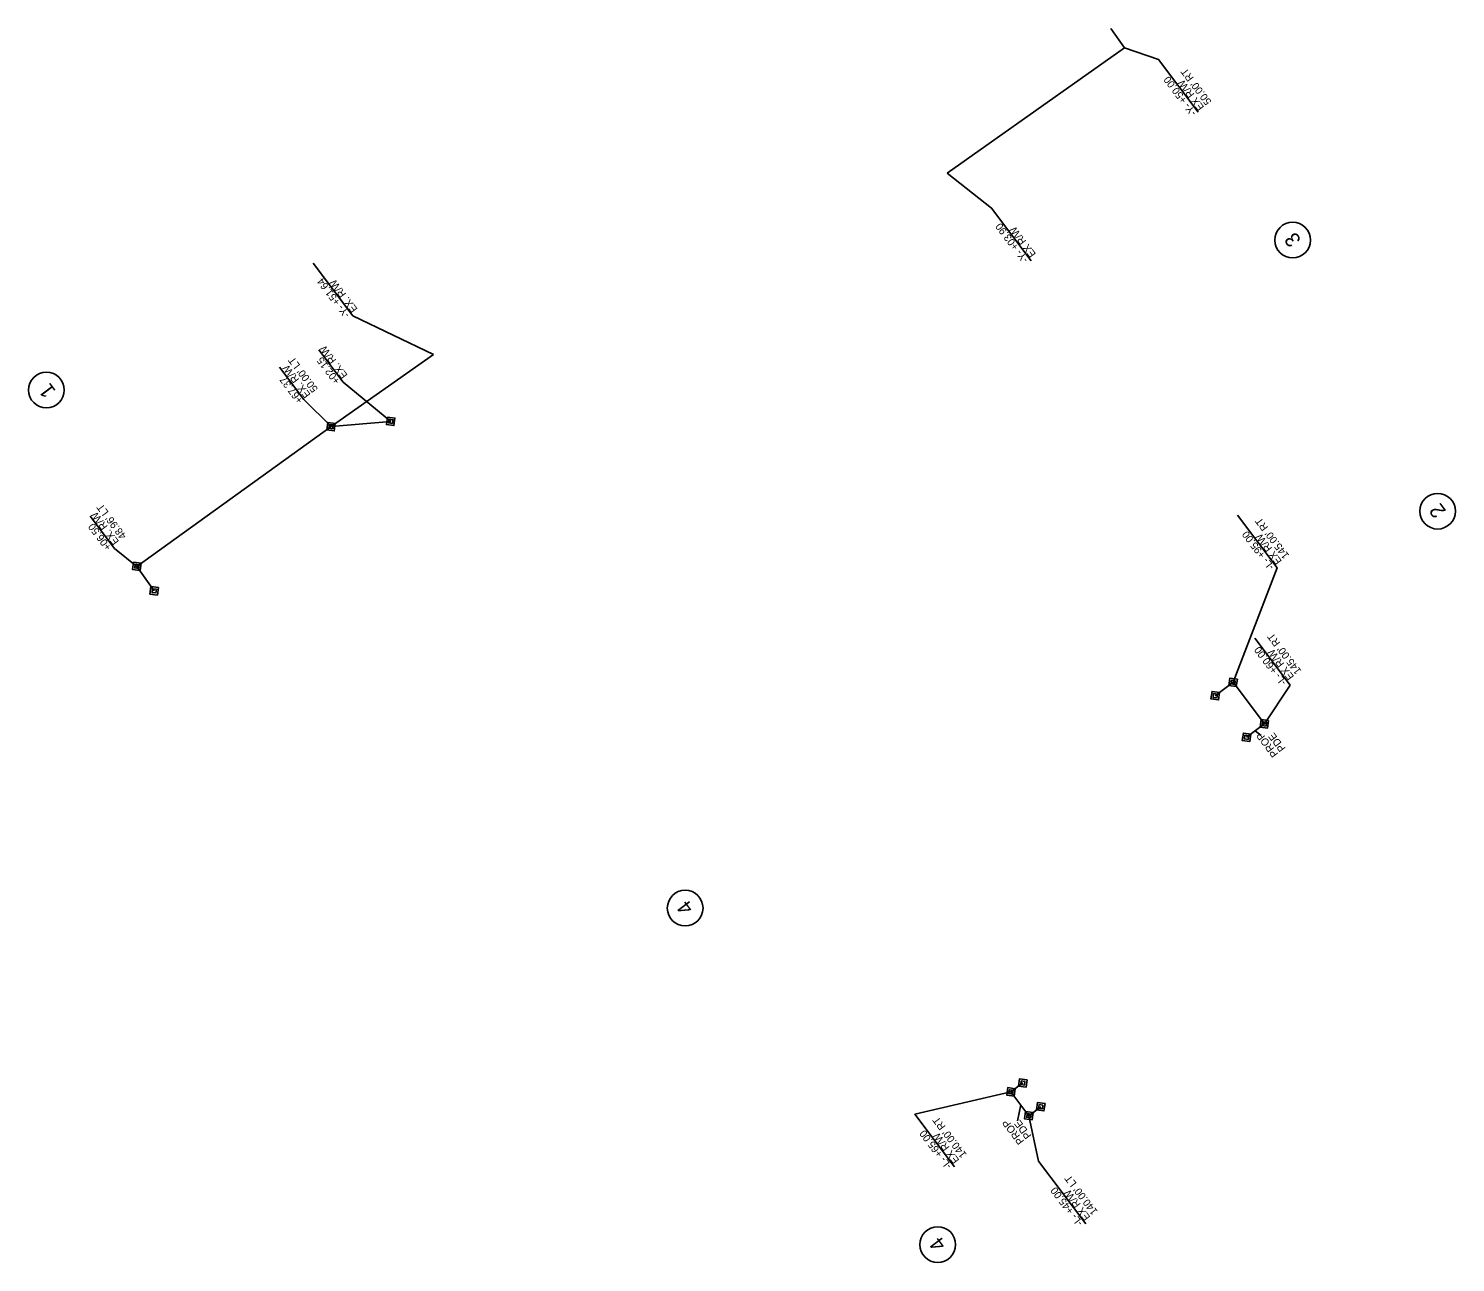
# Model space of a CAD drawing. Extents: x 1262953 to 1263913, y 775906 to 776736.
import ezdxf

# ---------------------------------------------------------------- set-up
doc = ezdxf.new("R2010")
doc.units = 0
for name, color, linetype in [('CTL Primary Horizontal and Vertical Cogo Elevation', 7, 'Continuous'), ('CTL Primary Horizontal and Vertical Cogo Number', 7, 'Continuous'), ('CTL Secondary Horizontal and Vertical CELL', 7, 'Continuous'), ('CTL Secondary Horizontal and Vertical Cogo Comment', 7, 'Continuous'), ('CTL Secondary Horizontal and Vertical Cogo Elevation', 7, 'Continuous'), ('CTL Secondary Horizontal and Vertical Cogo Number', 7, 'Continuous'), ('CTL Vertical Benchmark CELL', 7, 'Continuous'), ('CTL Vertical Benchmark Cogo Elevation', 7, 'Continuous'), ('CTL Vertical Benchmark Cogo Number', 7, 'Continuous')]:
    doc.layers.add(name, color=color, linetype=linetype)

msp = doc.modelspace()

# ---------------------------------------------------------------- linework, layer by layer
at = {"layer": 'CTL Primary Horizontal and Vertical Cogo Elevation'}
for p, q in [((1263156.87, 776467.92), (1263156.87, 776467.92)), ((1263196.98, 776471.45), (1263196.98, 776471.45)), ((1263026.3, 776373.94), (1263026.3, 776373.94)), ((1263037.95, 776357.47), (1263037.95, 776357.47)), ((1263763.41, 776295.97), (1263763.41, 776295.97)), ((1263751.43, 776286.95), (1263751.43, 776286.95)), ((1263784.47, 776268.02), (1263784.47, 776268.02)), ((1263772.49, 776258.99), (1263772.49, 776258.99)), ((1263622.05, 776026.56), (1263622.05, 776026.56)), ((1263614.07, 776020.55), (1263614.07, 776020.55)), ((1263626.1, 776004.57), (1263626.1, 776004.57)), ((1263634.09, 776010.59), (1263634.09, 776010.59))]:
    msp.add_line(p, q, dxfattribs=at)
for points in [[(1263194.8, 776474.31), (1263199.84, 776473.62), (1263199.16, 776468.58), (1263194.11, 776469.27)], [(1263159.73, 776470.09), (1263159.04, 776465.05), (1263154, 776465.74), (1263154.69, 776470.78)], [(1263158.3, 776469.01), (1263157.96, 776466.48), (1263155.43, 776466.83), (1263155.78, 776469.35)], [(1263195.89, 776472.88), (1263198.41, 776472.53), (1263198.07, 776470.01), (1263195.54, 776470.36)], [(1263024.12, 776376.81), (1263029.16, 776376.12), (1263028.47, 776371.08), (1263023.43, 776371.76)], [(1263025.21, 776375.38), (1263027.73, 776375.03), (1263027.39, 776372.51), (1263024.86, 776372.85)], [(1263035.77, 776360.34), (1263040.82, 776359.65), (1263040.13, 776354.61), (1263035.09, 776355.29)], [(1263036.86, 776358.9), (1263039.39, 776358.56), (1263039.04, 776356.04), (1263036.52, 776356.38)], [(1263766.28, 776298.15), (1263765.59, 776293.11), (1263760.55, 776293.79), (1263761.23, 776298.84)], [(1263764.84, 776297.06), (1263764.5, 776294.54), (1263761.98, 776294.88), (1263762.32, 776297.41)], [(1263754.29, 776289.13), (1263753.61, 776284.08), (1263748.56, 776284.77), (1263749.25, 776289.81)], [(1263752.86, 776288.04), (1263752.52, 776285.52), (1263750, 776285.86), (1263750.34, 776288.38)], [(1263787.33, 776270.19), (1263786.65, 776265.15), (1263781.6, 776265.84), (1263782.29, 776270.88)], [(1263785.9, 776269.11), (1263785.56, 776266.58), (1263783.04, 776266.93), (1263783.38, 776269.45)], [(1263775.35, 776261.17), (1263774.67, 776256.13), (1263769.62, 776256.81), (1263770.31, 776261.86)], [(1263773.92, 776260.08), (1263773.58, 776257.56), (1263771.05, 776257.9), (1263771.4, 776260.42)], [(1263616.93, 776022.72), (1263616.24, 776017.68), (1263611.2, 776018.37), (1263611.89, 776023.41)], [(1263624.92, 776028.74), (1263624.23, 776023.7), (1263619.19, 776024.38), (1263619.87, 776029.43)], [(1263623.49, 776027.65), (1263623.14, 776025.13), (1263620.62, 776025.47), (1263620.96, 776027.99)], [(1263615.5, 776021.64), (1263615.15, 776019.11), (1263612.63, 776019.46), (1263612.98, 776021.98)], [(1263636.95, 776012.77), (1263636.26, 776007.72), (1263631.22, 776008.41), (1263631.91, 776013.45)], [(1263628.96, 776006.75), (1263628.28, 776001.7), (1263623.23, 776002.39), (1263623.92, 776007.44)], [(1263627.53, 776005.66), (1263627.19, 776003.14), (1263624.67, 776003.48), (1263625.01, 776006)], [(1263635.52, 776011.68), (1263635.18, 776009.15), (1263632.65, 776009.5), (1263633, 776012.02)]]:
    msp.add_lwpolyline(points, close=True, dxfattribs=at)
at = {"layer": 'CTL Primary Horizontal and Vertical Cogo Number'}
for p, q in [((1263156.87, 776467.92), (1263026.3, 776373.94)), ((1263196.98, 776471.45), (1263156.87, 776467.92)), ((1263196.98, 776471.45), (1263196.98, 776471.45)), ((1263037.95, 776357.47), (1263026.3, 776373.94))]:
    msp.add_line(p, q, dxfattribs=at)
at = {"layer": 'CTL Secondary Horizontal and Vertical CELL'}
for points in [[(1263148.57, 776519.57), (1263164.91, 776497.89), (1263196.98, 776471.45)], [(1263122.25, 776507.79), (1263138.59, 776486.11), (1263156.87, 776467.92)], [(1262994.85, 776407.71), (1263011.19, 776386.03), (1263026.3, 776373.94)]]:
    msp.add_lwpolyline(points, dxfattribs=at)
at = {"layer": 'CTL Secondary Horizontal and Vertical Cogo Comment'}
for p, q in [((1263778.06, 776325.56), (1263801.81, 776294.03)), ((1263801.81, 776294.03), (1263784.47, 776268.02)), ((1263782.29, 776260.1), (1263778.36, 776263.42)), ((1263618.46, 776001.11), (1263620.65, 776011.8))]:
    msp.add_line(p, q, dxfattribs=at)
for points in [[(1263766.39, 776408.41), (1263793.09, 776372.96), (1263763.41, 776295.97)], [(1263614.07, 776020.55), (1263549.48, 776005.58), (1263576.18, 775970.13)], [(1263626.1, 776004.57), (1263632.57, 775973.96), (1263664.31, 775931.82)]]:
    msp.add_lwpolyline(points, dxfattribs=at)
at = {"layer": 'CTL Secondary Horizontal and Vertical Cogo Elevation'}
for points in [[(1263690.35, 776722.68), (1263713.3, 776714.7), (1263740, 776679.25)], [(1263571.1, 776638.28), (1263601.02, 776614.89), (1263627.72, 776579.44)], [(1263144.84, 776577.89), (1263171.54, 776542.44), (1263225.79, 776516.4)]]:
    msp.add_lwpolyline(points, dxfattribs=at)
at = {"layer": 'CTL Secondary Horizontal and Vertical Cogo Number'}
for p, q in [((1263690.35, 776722.68), (1263681.22, 776735.58)), ((1263690.35, 776722.68), (1263571.1, 776638.28)), ((1263225.79, 776516.4), (1263156.87, 776467.92))]:
    msp.add_line(p, q, dxfattribs=at)
at = {"layer": 'CTL Vertical Benchmark CELL'}
for p, q in [((1263803.46, 776593.32), (1263803.46, 776593.32)), ((1262965.44, 776492.5), (1262965.44, 776492.5)), ((1263900.95, 776411.03), (1263900.95, 776411.03)), ((1263394.98, 776144.15), (1263394.98, 776144.15)), ((1263564.8, 775917.87), (1263564.8, 775917.87))]:
    msp.add_line(p, q, dxfattribs=at)
for centre in [(1263803.46, 776593.32), (1262965.44, 776492.5), (1263900.95, 776411.03), (1263394.98, 776144.15), (1263564.8, 775917.87)]:
    msp.add_circle(centre, 12, dxfattribs=at)
at = {"layer": 'CTL Vertical Benchmark Cogo Elevation'}
for p, q in [((1263763.41, 776295.97), (1263751.43, 776286.95)), ((1263763.41, 776295.97), (1263784.47, 776268.02)), ((1263784.47, 776268.02), (1263772.49, 776258.99)), ((1263614.07, 776020.55), (1263622.05, 776026.56)), ((1263626.1, 776004.57), (1263614.07, 776020.55)), ((1263634.09, 776010.59), (1263626.1, 776004.57))]:
    msp.add_line(p, q, dxfattribs=at)

# ---------------------------------------------------------------- texts
at = {"layer": 'CTL Secondary Horizontal and Vertical CELL'}
for s, p in [('EX. R/W', (1263168.24, 776502.52)), ("50.00' LT", (1263148.33, 776493.23)), ('+02.15', (1263163.25, 776498.76)), ('EX. R/W', (1263143.33, 776489.47)), ('+67.37', (1263138.34, 776485.71)), ('EX. R/W', (1263014.53, 776390.67)), ("48.96' LT", (1263019.52, 776394.43)), ('+06.50', (1263009.53, 776386.91))]:
    msp.add_text(s, height=5, rotation=126.98742, dxfattribs=at).set_placement(p)
at = {"layer": 'CTL Secondary Horizontal and Vertical Cogo Comment'}
for s, p in [('-L- +95.00', (1263791.45, 776373.75)), ("145.00' RT", (1263801.43, 776381.27)), ('EX R/W', (1263796.44, 776377.51)), ("145.00' RT", (1263809.62, 776303.61)), ('-L- +60.00', (1263799.64, 776296.09)), ('EX R/W', (1263804.63, 776299.85)), ('PDE', (1263799, 776251.61)), ('PROP', (1263794.01, 776247.85)), ('-L- +65.00', (1263574.54, 775970.92)), ("140.00' RT", (1263584.53, 775978.44)), ('PROP', (1263623.16, 775987.47)), ('PDE', (1263628.16, 775991.23)), ('EX R/W', (1263579.54, 775974.68)), ('-L- +45.00', (1263662.67, 775932.61)), ("140.00' LT", (1263672.66, 775940.13)), ('EX R/W', (1263667.66, 775936.37))]:
    msp.add_text(s, height=5, rotation=126.98742, dxfattribs=at).set_placement(p)
at = {"layer": 'CTL Secondary Horizontal and Vertical Cogo Elevation'}
for s, p in [("50.00' RT", (1263749.16, 776686.48)), ('-Y- +50.00', (1263739.17, 776678.96)), ('EX R/W', (1263744.17, 776682.72)), ('-Y- +03.90', (1263626.08, 776580.23)), ('EX R/W', (1263631.08, 776583.99)), ('-Y- +51.64', (1263169.9, 776543.23)), ('EX. R/W', (1263174.89, 776546.99))]:
    msp.add_text(s, height=5, rotation=126.98742, dxfattribs=at).set_placement(p)
at = {"layer": 'CTL Vertical Benchmark Cogo Number'}
for s, p in [('3', (1263809.6, 776593.48)), ('1', (1262972.15, 776491.91)), ('2', (1263907.05, 776411.23)), ('4', (1263401.1, 776144.32)), ('4', (1263570.93, 775918.05))]:
    msp.add_text(s, height=10, rotation=126.98742, dxfattribs=at).set_placement(p)

doc.saveas('drawing.dxf')
